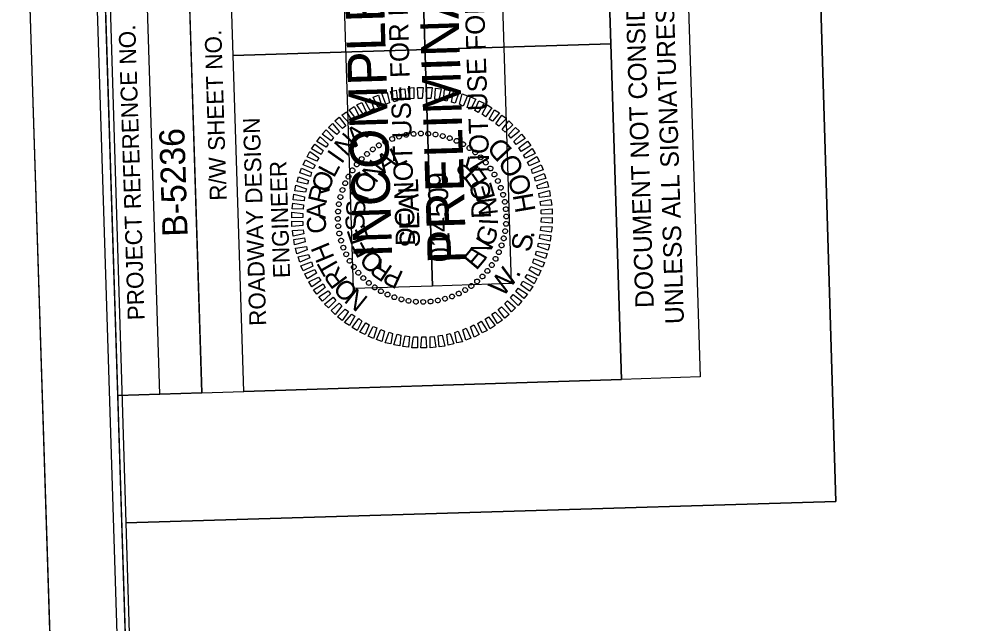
# Model space of a CAD drawing. Extents: x 2326025 to 2327173, y 123144 to 125024.
# Drawn here: x 2326025.5 to 2326312.3, y 124704.9 to 124884.9 of the extents above; entities that cross this region are included whole.
import ezdxf

# ---------------------------------------------------------------- set-up
doc = ezdxf.new("R2010")
doc.units = 0
for name, color, linetype in [('Sheet Clip Boundary CELL', 7, 'Continuous'), ('Sheet Cutting Line CELL', 7, 'Continuous'), ('Sheet Data Field CELL', 7, 'Continuous'), ('Sheet Layout Plan Border', 7, 'Continuous'), ('Sheet PE Seal Cell', 7, 'Continuous'), ('Sheet Plan CELL', 7, 'Continuous'), ('Sheet Plan Layout CELL', 7, 'Continuous'), ('Sheet Plot Border Inside CELL', 7, 'Continuous'), ('Sheet Plot Border Outside CELL', 7, 'Continuous'), ('Sheet Sticker Exception Certification CELL', 7, 'Continuous'), ('Sheet Sticker Incomplete CELL', 7, 'Continuous'), ('Sheet Sticker Preliminary CELL', 7, 'Continuous'), ('Typical Detail Wedge2 CELL', 7, 'Continuous')]:
    doc.layers.add(name, color=color, linetype=linetype)

msp = doc.modelspace()

# ---------------------------------------------------------------- linework, layer by layer
at = {"layer": 'Sheet Clip Boundary CELL'}
msp.add_lwpolyline([(2327143.22, 123556.44), (2327101.01, 124955.82), (2326262.87, 124930.53), (2326268.58, 124741.36), (2326057.19, 124734.98), (2326093.7, 123524.78)], close=True, dxfattribs=at)
at = {"layer": 'Sheet Cutting Line CELL'}
msp.add_line((2326025.47, 124989.14), (2326078.49, 123306.48), dxfattribs=at)
at = {"layer": 'Sheet Layout Plan Border'}
msp.add_lwpolyline([(2327143.22, 123556.44), (2327101.01, 124955.82), (2326262.87, 124930.53), (2326268.58, 124741.36), (2326057.19, 124734.98), (2326093.7, 123524.78)], close=True, dxfattribs=at)
at = {"layer": 'Sheet PE Seal Cell'}
for p, q in [((2326134.48, 124848.43), (2326134.48, 124848.43)), ((2326136.45, 124849.3), (2326136.45, 124849.3)), ((2326138.53, 124849.96), (2326138.53, 124849.96)), ((2326140.72, 124850.43), (2326140.72, 124850.43)), ((2326142.86, 124850.8), (2326142.86, 124850.8)), ((2326145.06, 124850.92), (2326145.06, 124850.92)), ((2326147.26, 124850.84), (2326147.26, 124850.84)), ((2326149.42, 124850.56), (2326149.42, 124850.56)), ((2326151.53, 124850.17), (2326151.53, 124850.17)), ((2326153.66, 124849.54), (2326153.66, 124849.54)), ((2326155.68, 124848.7), (2326155.68, 124848.7)), ((2326130.7, 124846.16), (2326130.7, 124846.16)), ((2326132.56, 124847.37), (2326132.56, 124847.37)), ((2326157.66, 124847.76), (2326157.66, 124847.76)), ((2326159.5, 124846.57), (2326159.5, 124846.57)), ((2326127.39, 124843.31), (2326127.39, 124843.31)), ((2326128.99, 124844.86), (2326128.99, 124844.86)), ((2326161.29, 124845.28), (2326161.29, 124845.28)), ((2326162.89, 124843.83), (2326162.89, 124843.83)), ((2326124.64, 124839.92), (2326124.64, 124839.92)), ((2326125.94, 124841.71), (2326125.94, 124841.71)), ((2326164.44, 124842.22), (2326164.44, 124842.22)), ((2326165.75, 124840.52), (2326165.75, 124840.52)), ((2326123.45, 124838.08), (2326123.45, 124838.08)), ((2326166.95, 124838.65), (2326166.95, 124838.65)), ((2326121.68, 124834.07), (2326121.68, 124834.07)), ((2326122.51, 124836.1), (2326122.51, 124836.1)), ((2326168.02, 124836.73), (2326168.02, 124836.73)), ((2326168.88, 124834.76), (2326168.88, 124834.76)), ((2326121.04, 124831.95), (2326121.04, 124831.95)), ((2326169.54, 124832.68), (2326169.54, 124832.68)), ((2326120.66, 124829.84), (2326120.66, 124829.84)), ((2326170.01, 124830.49), (2326170.01, 124830.49)), ((2326170.38, 124828.35), (2326170.38, 124828.35)), ((2326120.3, 124825.48), (2326120.3, 124825.48)), ((2326120.38, 124827.68), (2326120.38, 124827.68)), ((2326145.4, 124825.82), (2326145.4, 124825.82)), ((2326170.5, 124826.16), (2326170.5, 124826.16)), ((2326120.42, 124823.28), (2326120.42, 124823.28)), ((2326170.42, 124823.95), (2326170.42, 124823.95)), ((2326120.78, 124821.14), (2326120.78, 124821.14)), ((2326169.75, 124819.68), (2326169.75, 124819.68)), ((2326170.14, 124821.79), (2326170.14, 124821.79)), ((2326121.25, 124818.95), (2326121.25, 124818.95)), ((2326121.92, 124816.87), (2326121.92, 124816.87)), ((2326169.12, 124817.56), (2326169.12, 124817.56)), ((2326122.78, 124814.9), (2326122.78, 124814.9)), ((2326168.28, 124815.53), (2326168.28, 124815.53)), ((2326123.84, 124812.98), (2326123.84, 124812.98)), ((2326125.05, 124811.12), (2326125.05, 124811.12)), ((2326166.15, 124811.71), (2326166.15, 124811.71)), ((2326167.35, 124813.55), (2326167.35, 124813.55)), ((2326126.36, 124809.41), (2326126.36, 124809.41)), ((2326163.41, 124808.33), (2326163.41, 124808.33)), ((2326164.86, 124809.92), (2326164.86, 124809.92)), ((2326127.91, 124807.81), (2326127.91, 124807.81)), ((2326129.5, 124806.36), (2326129.5, 124806.36)), ((2326160.1, 124805.47), (2326160.1, 124805.47)), ((2326161.81, 124806.77), (2326161.81, 124806.77)), ((2326131.29, 124805.06), (2326131.29, 124805.06)), ((2326133.13, 124803.87), (2326133.13, 124803.87)), ((2326135.11, 124802.93), (2326135.11, 124802.93)), ((2326156.32, 124803.2), (2326156.32, 124803.2)), ((2326158.23, 124804.26), (2326158.23, 124804.26)), ((2326137.14, 124802.1), (2326137.14, 124802.1)), ((2326139.26, 124801.46), (2326139.26, 124801.46)), ((2326141.38, 124801.08), (2326141.38, 124801.08)), ((2326143.54, 124800.8), (2326143.54, 124800.8)), ((2326145.74, 124800.72), (2326145.74, 124800.72)), ((2326147.94, 124800.83), (2326147.94, 124800.83)), ((2326150.08, 124801.2), (2326150.08, 124801.2)), ((2326152.26, 124801.67), (2326152.26, 124801.67)), ((2326154.34, 124802.34), (2326154.34, 124802.34))]:
    msp.add_line(p, q, dxfattribs=at)
for points in [[(2326134.63, 124859.59), (2326133.38, 124862.76), (2326135.02, 124863.11), (2326135.67, 124859.98)], [(2326137.01, 124860.27), (2326135.96, 124863.39), (2326137.65, 124863.74), (2326138.05, 124860.6)], [(2326139.39, 124860.8), (2326138.59, 124864.02), (2326140.29, 124864.22), (2326140.59, 124861.03)], [(2326141.78, 124861.17), (2326141.28, 124864.41), (2326142.98, 124864.56), (2326142.98, 124861.31)], [(2326144.28, 124861.3), (2326144.03, 124864.54), (2326145.73, 124864.6), (2326145.48, 124861.34)], [(2326146.78, 124861.33), (2326146.78, 124864.58), (2326148.43, 124864.53), (2326147.98, 124861.27)], [(2326149.19, 124861.15), (2326149.39, 124864.36), (2326151.09, 124864.22), (2326150.39, 124860.94)], [(2326151.75, 124860.83), (2326152.05, 124863.95), (2326153.76, 124863.65), (2326152.81, 124860.47)], [(2326154.17, 124860.26), (2326154.72, 124863.38), (2326156.38, 124863.08), (2326155.23, 124859.89)], [(2326156.59, 124859.59), (2326157.39, 124862.71), (2326158.96, 124862.11), (2326157.66, 124859.07)], [(2326127.82, 124856.68), (2326125.98, 124859.42), (2326127.51, 124860.12), (2326128.75, 124857.31)], [(2326129.94, 124857.75), (2326128.34, 124860.65), (2326129.92, 124861.35), (2326131.02, 124858.28)], [(2326132.26, 124858.72), (2326130.86, 124861.73), (2326132.39, 124862.33), (2326133.29, 124859.25)], [(2326158.82, 124858.66), (2326159.87, 124861.79), (2326161.45, 124861.09), (2326159.94, 124858.19)], [(2326161.15, 124857.73), (2326162.31, 124860.62), (2326163.88, 124859.92), (2326162.12, 124857.16)], [(2326123.65, 124853.95), (2326121.48, 124856.33), (2326122.89, 124857.32), (2326124.58, 124854.58)], [(2326125.66, 124855.31), (2326123.68, 124857.9), (2326125.15, 124858.9), (2326126.64, 124856.04)], [(2326163.34, 124856.6), (2326164.75, 124859.44), (2326166.18, 124858.49), (2326164.26, 124855.83)], [(2326165.38, 124855.16), (2326167, 124857.91), (2326168.48, 124857.01), (2326166.35, 124854.54)], [(2326121.75, 124852.39), (2326119.43, 124854.61), (2326120.74, 124855.71), (2326122.73, 124853.12)], [(2326167.33, 124853.72), (2326169.2, 124856.38), (2326170.53, 124855.32), (2326168.25, 124853.05)], [(2326169.28, 124852.03), (2326171.25, 124854.65), (2326172.44, 124853.43), (2326170.11, 124851.26)], [(2326118.31, 124848.73), (2326115.65, 124850.69), (2326116.81, 124851.93), (2326119.03, 124849.7)], [(2326120.01, 124850.58), (2326117.59, 124852.65), (2326118.75, 124853.89), (2326120.78, 124851.35)], [(2326171.09, 124850.44), (2326173.22, 124852.71), (2326174.45, 124851.54), (2326171.82, 124849.51)], [(2326116.82, 124846.78), (2326114.02, 124848.54), (2326115.08, 124849.87), (2326117.49, 124847.75)], [(2326172.7, 124848.49), (2326175.03, 124850.71), (2326176.12, 124849.4), (2326173.38, 124847.56)], [(2326174.26, 124846.64), (2326176.75, 124848.57), (2326177.74, 124847.3), (2326174.89, 124845.56)], [(2326114.1, 124842.69), (2326111.21, 124843.95), (2326112.01, 124845.48), (2326114.67, 124843.66)], [(2326115.39, 124844.68), (2326112.44, 124846.34), (2326113.44, 124847.67), (2326115.95, 124845.8)], [(2326175.58, 124844.48), (2326178.22, 124846.41), (2326179.06, 124844.89), (2326176.21, 124843.55)], [(2326113.02, 124840.35), (2326110.04, 124841.51), (2326110.69, 124843.08), (2326113.54, 124841.47)], [(2326176.84, 124842.37), (2326179.59, 124844.05), (2326180.34, 124842.53), (2326177.33, 124841.28)], [(2326112.15, 124838.08), (2326108.96, 124839.13), (2326109.52, 124840.54), (2326112.46, 124839.24)], [(2326177.96, 124840.2), (2326180.82, 124841.59), (2326181.47, 124840.11), (2326178.3, 124838.96)], [(2326111.32, 124835.8), (2326108.19, 124836.45), (2326108.65, 124838.02), (2326111.63, 124836.86)], [(2326178.84, 124837.78), (2326181.8, 124839.02), (2326182.3, 124837.48), (2326179.22, 124836.74)], [(2326110.74, 124833.38), (2326107.48, 124833.78), (2326107.83, 124835.49), (2326110.96, 124834.44)], [(2326179.56, 124835.4), (2326182.68, 124836.55), (2326183.08, 124834.86), (2326179.85, 124834.36)], [(2326110.27, 124830.81), (2326107.06, 124831.16), (2326107.26, 124832.82), (2326110.39, 124832.02)], [(2326180.19, 124833.02), (2326183.36, 124833.92), (2326183.56, 124832.27), (2326180.38, 124831.82)], [(2326180.56, 124830.63), (2326183.75, 124831.28), (2326184, 124829.58), (2326180.75, 124829.43)], [(2326109.95, 124828.4), (2326106.69, 124828.5), (2326106.94, 124830.16), (2326110.11, 124829.61)], [(2326180.89, 124828.14), (2326184.13, 124828.49), (2326184.14, 124826.84), (2326180.88, 124826.93)], [(2326109.88, 124825.9), (2326106.63, 124825.8), (2326106.63, 124827.45), (2326109.89, 124827.1)], [(2326180.92, 124825.74), (2326184.17, 124825.84), (2326184.17, 124824.19), (2326180.91, 124824.53)], [(2326109.9, 124823.5), (2326106.66, 124823.15), (2326106.66, 124824.8), (2326109.92, 124824.7)], [(2326180.85, 124823.23), (2326184.1, 124823.13), (2326183.85, 124821.48), (2326180.69, 124822.03)], [(2326110.23, 124821.01), (2326107.05, 124820.36), (2326106.8, 124822.05), (2326110.04, 124822.2)], [(2326110.61, 124818.62), (2326107.43, 124817.72), (2326107.23, 124819.36), (2326110.42, 124819.81)], [(2326180.52, 124820.82), (2326183.74, 124820.47), (2326183.54, 124818.81), (2326180.41, 124819.62)], [(2326111.23, 124816.24), (2326108.12, 124815.09), (2326107.71, 124816.78), (2326110.95, 124817.28)], [(2326180.05, 124818.25), (2326183.32, 124817.86), (2326182.97, 124816.15), (2326179.84, 124817.2)], [(2326111.96, 124813.86), (2326109, 124812.61), (2326108.5, 124814.15), (2326111.58, 124814.9)], [(2326179.48, 124815.84), (2326182.6, 124815.18), (2326182.15, 124813.62), (2326179.16, 124814.77)], [(2326112.84, 124811.43), (2326109.98, 124810.04), (2326109.33, 124811.52), (2326112.5, 124812.67)], [(2326177.77, 124811.28), (2326180.76, 124810.12), (2326180.11, 124808.55), (2326177.26, 124810.16)], [(2326178.65, 124813.56), (2326181.84, 124812.51), (2326181.28, 124811.09), (2326178.34, 124812.4)], [(2326113.95, 124809.27), (2326111.21, 124807.58), (2326110.46, 124809.11), (2326113.47, 124810.35)], [(2326176.7, 124808.94), (2326179.59, 124807.68), (2326178.78, 124806.16), (2326176.13, 124807.98)], [(2326115.22, 124807.16), (2326112.58, 124805.22), (2326111.73, 124806.75), (2326114.59, 124808.09)], [(2326116.54, 124805), (2326114.05, 124803.07), (2326113.06, 124804.34), (2326115.91, 124806.08)], [(2326175.41, 124806.95), (2326178.36, 124805.29), (2326177.35, 124803.96), (2326174.84, 124805.83)], [(2326118.1, 124803.15), (2326115.77, 124800.92), (2326114.68, 124802.24), (2326117.42, 124804.07)], [(2326172.48, 124802.91), (2326175.15, 124800.94), (2326173.98, 124799.7), (2326171.76, 124801.94)], [(2326173.97, 124804.86), (2326176.78, 124803.09), (2326175.72, 124801.76), (2326173.3, 124803.88)], [(2326119.71, 124801.2), (2326117.58, 124798.93), (2326116.34, 124800.09), (2326118.98, 124802.12)], [(2326121.51, 124799.6), (2326119.54, 124796.99), (2326118.35, 124798.2), (2326120.69, 124800.38)], [(2326170.79, 124801.05), (2326173.21, 124798.98), (2326172.05, 124797.74), (2326170.01, 124800.28)], [(2326123.47, 124797.91), (2326121.6, 124795.25), (2326120.27, 124796.31), (2326122.54, 124798.58)], [(2326125.41, 124796.47), (2326123.8, 124793.72), (2326122.32, 124794.62), (2326124.44, 124797.09)], [(2326167.15, 124797.69), (2326169.32, 124795.31), (2326167.9, 124794.31), (2326166.21, 124797.06)], [(2326169.05, 124799.25), (2326171.37, 124797.02), (2326170.05, 124795.93), (2326168.07, 124798.52)], [(2326127.46, 124795.04), (2326126.05, 124792.19), (2326124.62, 124793.15), (2326126.53, 124795.81)], [(2326129.65, 124793.9), (2326128.49, 124791.02), (2326126.91, 124791.72), (2326128.68, 124794.47)], [(2326160.86, 124793.89), (2326162.45, 124790.99), (2326160.88, 124790.29), (2326159.78, 124793.35)], [(2326162.98, 124794.96), (2326164.82, 124792.21), (2326163.29, 124791.51), (2326162.05, 124794.33)], [(2326165.14, 124796.32), (2326167.12, 124793.74), (2326165.65, 124792.74), (2326164.16, 124795.59)], [(2326131.98, 124792.98), (2326130.92, 124789.84), (2326129.35, 124790.54), (2326130.86, 124793.44)], [(2326134.21, 124792.05), (2326133.4, 124788.92), (2326131.83, 124789.52), (2326133.14, 124792.56)], [(2326136.63, 124791.37), (2326136.08, 124788.25), (2326134.42, 124788.55), (2326135.57, 124791.74)], [(2326139.05, 124790.8), (2326138.75, 124787.69), (2326137.04, 124787.98), (2326137.99, 124791.17)], [(2326153.79, 124791.36), (2326154.84, 124788.25), (2326153.15, 124787.89), (2326152.75, 124791.03)], [(2326156.17, 124792.04), (2326157.42, 124788.88), (2326155.78, 124788.53), (2326155.13, 124791.66)], [(2326158.54, 124792.91), (2326159.94, 124789.91), (2326158.4, 124789.31), (2326157.51, 124792.38)], [(2326141.61, 124790.48), (2326141.41, 124787.27), (2326139.7, 124787.42), (2326140.4, 124790.69)], [(2326144.02, 124790.31), (2326144.02, 124787.05), (2326142.37, 124787.1), (2326142.81, 124790.37)], [(2326146.52, 124790.33), (2326146.77, 124787.09), (2326145.07, 124787.04), (2326145.32, 124790.3)], [(2326149.01, 124790.46), (2326149.52, 124787.23), (2326147.82, 124787.07), (2326147.82, 124790.33)], [(2326151.4, 124790.84), (2326152.2, 124787.61), (2326150.51, 124787.41), (2326150.21, 124790.6)]]:
    msp.add_lwpolyline(points, close=True, dxfattribs=at)
for centre, major_axis in [((2326140.7, 124850.45), (-0.135, 0.707)), ((2326142.86, 124850.77), (-0.073, 0.716)), ((2326145.05, 124850.89), (-0.01, 0.72)), ((2326147.23, 124850.83), (0.053, 0.718)), ((2326149.41, 124850.57), (0.115, 0.711)), ((2326134.48, 124848.4), (-0.313, 0.648)), ((2326136.49, 124849.26), (-0.256, 0.673)), ((2326138.57, 124849.95), (-0.196, 0.693)), ((2326151.55, 124850.13), (0.177, 0.698)), ((2326153.64, 124849.5), (0.237, 0.68)), ((2326155.68, 124848.69), (0.295, 0.657)), ((2326157.63, 124847.71), (0.351, 0.629)), ((2326129.01, 124844.8), (-0.471, 0.545)), ((2326130.73, 124846.16), (-0.421, 0.584)), ((2326132.55, 124847.36), (-0.369, 0.618)), ((2326159.49, 124846.56), (0.405, 0.596)), ((2326161.25, 124845.25), (0.455, 0.558)), ((2326127.42, 124843.3), (-0.516, 0.502)), ((2326162.88, 124843.8), (0.502, 0.516)), ((2326164.38, 124842.21), (0.545, 0.471)), ((2326124.65, 124839.91), (-0.596, 0.405)), ((2326125.96, 124841.67), (-0.558, 0.455)), ((2326165.74, 124840.49), (0.584, 0.421)), ((2326122.52, 124836.1), (-0.657, 0.295)), ((2326123.5, 124838.05), (-0.629, 0.351)), ((2326166.94, 124838.66), (0.618, 0.369)), ((2326167.98, 124836.73), (0.648, 0.313)), ((2326121.71, 124834.06), (-0.68, 0.237)), ((2326168.84, 124834.72), (0.673, 0.256)), ((2326121.08, 124831.97), (-0.698, 0.177)), ((2326169.53, 124832.65), (0.693, 0.196)), ((2326170.03, 124830.52), (0.707, 0.135)), ((2326120.39, 124827.65), (-0.718, 0.053)), ((2326120.64, 124829.82), (-0.711, 0.115)), ((2326170.35, 124828.35), (0.716, 0.073)), ((2326120.32, 124825.46), (-0.72, -0.01)), ((2326170.48, 124826.17), (0.72, 0.01)), ((2326120.45, 124823.28), (-0.716, -0.073)), ((2326170.16, 124821.81), (0.711, -0.115)), ((2326170.41, 124823.98), (0.718, -0.053)), ((2326120.76, 124821.12), (-0.707, -0.135)), ((2326121.27, 124818.99), (-0.693, -0.196)), ((2326169.71, 124819.67), (0.698, -0.177)), ((2326121.95, 124816.91), (-0.673, -0.256)), ((2326169.08, 124817.57), (0.68, -0.237)), ((2326122.82, 124814.9), (-0.648, -0.313)), ((2326167.29, 124813.58), (0.629, -0.351)), ((2326168.28, 124815.54), (0.657, -0.295)), ((2326123.86, 124812.97), (-0.618, -0.369)), ((2326125.06, 124811.14), (-0.584, -0.421)), ((2326166.14, 124811.72), (0.596, -0.405)), ((2326126.41, 124809.43), (-0.545, -0.471)), ((2326127.91, 124807.84), (-0.502, -0.516)), ((2326163.38, 124808.33), (0.516, -0.502)), ((2326164.84, 124809.97), (0.558, -0.455)), ((2326129.55, 124806.38), (-0.455, -0.558)), ((2326131.3, 124805.07), (-0.405, -0.596)), ((2326160.07, 124805.48), (0.421, -0.584)), ((2326161.79, 124806.83), (0.471, -0.545)), ((2326133.16, 124803.92), (-0.351, -0.629)), ((2326135.12, 124802.94), (-0.295, -0.657)), ((2326137.15, 124802.13), (-0.237, -0.68)), ((2326152.23, 124801.69), (0.196, -0.693)), ((2326154.31, 124802.37), (0.256, -0.673)), ((2326156.32, 124803.24), (0.313, -0.648)), ((2326158.24, 124804.28), (0.369, -0.618)), ((2326139.25, 124801.5), (-0.177, -0.698)), ((2326141.39, 124801.06), (-0.115, -0.711)), ((2326143.56, 124800.8), (-0.053, -0.718)), ((2326145.75, 124800.74), (0.01, -0.72)), ((2326147.93, 124800.87), (0.073, -0.716)), ((2326150.1, 124801.18), (0.135, -0.707))]:
    msp.add_ellipse(centre, major_axis=major_axis, ratio=0.999708, dxfattribs=at)
at = {"layer": 'Sheet Plan CELL'}
for p, q in [((2326067.31, 124773.29), (2326061.02, 124973.24)), ((2326079.84, 124773.7), (2326073.52, 124973.64)), ((2326079.84, 124773.7), (2326073.52, 124973.64)), ((2326089.17, 124874.09), (2326201.58, 124877.65)), ((2326079.84, 124773.7), (2326092.32, 124774.09))]:
    msp.add_line(p, q, dxfattribs=at)
for points in [[(2326048.48, 124972.88), (2326095.72, 123473.59), (2327145.2, 123506.66), (2327097.96, 125005.93)], [(2327145.2, 123506.66), (2326095.75, 123473.57), (2326054.77, 124772.91), (2326204.76, 124777.65), (2326198.47, 124977.58), (2327097.96, 125005.93)], [(2326089.17, 124874.09), (2326086.01, 124974.03), (2326198.47, 124977.58), (2326201.63, 124877.63)], [(2326054.77, 124772.91), (2326048.48, 124972.88), (2326073.52, 124973.64), (2326079.84, 124773.7)], [(2326092.32, 124774.09), (2326089.17, 124874.09), (2326201.63, 124877.63), (2326204.76, 124777.65)]]:
    msp.add_lwpolyline(points, close=True, dxfattribs=at)
at = {"layer": 'Sheet Plan Layout CELL'}
for points in [[(2326095.24, 123474.78), (2327144.73, 123506.47), (2327099.5, 125005.78), (2326261.37, 124980.5), (2326268.58, 124741.36), (2326057.19, 124734.98)], [(2326268.58, 124741.36), (2326261.37, 124980.52), (2326049.97, 124974.17), (2326057.19, 124734.98)]]:
    msp.add_lwpolyline(points, close=True, dxfattribs=at)
at = {"layer": 'Sheet Plot Border Inside CELL'}
msp.add_lwpolyline([(2327152.55, 123353.33), (2327100.07, 125018.49), (2326045.6, 124985.27), (2326098.07, 123320.1)], close=True, dxfattribs=at)
at = {"layer": 'Sheet Plot Border Outside CELL'}
msp.add_lwpolyline([(2327172.95, 123340.96), (2327119.93, 125023.63), (2326025.47, 124989.14), (2326078.49, 123306.48)], close=True, dxfattribs=at)
at = {"layer": 'Sheet Sticker Exception Certification CELL'}
for p, q in [((2326204.76, 124777.65), (2326198.46, 124977.58)), ((2326221.94, 124978.32), (2326228.24, 124778.39)), ((2326228.24, 124778.39), (2326204.76, 124777.65))]:
    msp.add_line(p, q, dxfattribs=at)
at = {"layer": 'Sheet Sticker Incomplete CELL'}
msp.add_lwpolyline([(2326148.48, 124805.44), (2326124.99, 124804.7), (2326120.36, 124951.63), (2326143.85, 124952.37)], close=True, dxfattribs=at)
at = {"layer": 'Sheet Sticker Preliminary CELL'}
msp.add_lwpolyline([(2326171.97, 124806.18), (2326148.48, 124805.44), (2326143.85, 124952.37), (2326167.34, 124953.11)], close=True, dxfattribs=at)

# ---------------------------------------------------------------- texts
at = {"layer": 'Sheet Data Field CELL'}
msp.add_text('B-5236', height=7.5, rotation=91.8048, dxfattribs=at).set_placement((2326075.61, 124820.26))
at = {"layer": 'Sheet PE Seal Cell'}
for s, height, rotation, p in [('A', 5.64, 40.4219, (2326125.78, 124846.81)), ('N', 5.64, 47.6237, (2326122.92, 124843.77)), ('I', 5.64, 54.8249, (2326121.44, 124841.57)), ('L', 5.64, 24.2056, (2326137.47, 124840.82)), ('N', 5.64, 52.2814, (2326131.58, 124835.84)), ('A', 5.64, 33.5651, (2326134.08, 124838.77)), ('R', 5.64, 134.2862, (2326162.7, 124840.47)), ('L', 5.64, 62.0257, (2326119.17, 124837.45)), ('E', 5.64, 124.9289, (2326165.16, 124836.99)), ('O', 5.64, 69.226, (2326117.46, 124832.99)), ('O', 5.64, 61.6383, (2326129.68, 124832.43)), ('SEAL', 5.998, 91.8048, (2326144.83, 124817)), ('014509', 5.998, 91.8048, (2326153.82, 124812.69)), ('R', 5.64, 76.4259, (2326116.81, 124829.62)), ('E', 5.64, 106.2166, (2326167.27, 124831.76)), ('I', 5.64, 70.9944, (2326129.05, 124830.4)), ('N', 5.64, 96.8612, (2326168.03, 124826.83)), ('A', 5.64, 90.8251, (2326116.75, 124825.41)), ('S', 5.64, 89.7052, (2326128.48, 124826.08)), ('C', 5.64, 98.0247, (2326117.17, 124821.48)), ('S', 5.64, 99.0604, (2326128.64, 124822.49)), ('E', 5.64, 108.4159, (2326129.8, 124819.07)), ('G', 5.64, 68.795, (2326166.29, 124816.87)), ('I', 5.64, 87.506, (2326167.98, 124823.48)), ('N', 5.64, 59.4387, (2326164.16, 124813)), ('H', 5.64, 112.4243, (2326119.41, 124813.94)), ('F', 5.64, 117.7718, (2326131.4, 124815.92)), ('E', 5.64, 50.0817, (2326161.56, 124809.92)), ('O', 5.64, 136.486, (2326134.46, 124812.72)), ('R', 5.64, 145.8444, (2326136.96, 124811.04)), ('T', 5.64, 119.6246, (2326121.16, 124810.75)), ('R', 5.64, 126.8253, (2326123.47, 124807.42)), ('P', 5.64, 155.2037, (2326140.21, 124809.55)), ('O', 5.64, 134.0265, (2326126.67, 124804.07)), ('N', 5.64, 141.2283, (2326129.65, 124801.86))]:
    msp.add_text(s, height=height, rotation=rotation, dxfattribs=at).set_placement(p)
at = {"layer": 'Sheet Plan CELL'}
for s, height, p in [('PROJECT REFERENCE NO.', 5.0001, (2326062.79, 124795.37)), ('R/W SHEET NO.', 5.0001, (2326087.23, 124830.96)), ('ROADWAY DESIGN', 5.0001, (2326099.01, 124793.69)), ('ENGINEER', 5, (2326106.1, 124807.9))]:
    msp.add_text(s, height=height, rotation=91.8048, dxfattribs=at).set_placement(p)
at = {"layer": 'Sheet Sticker Exception Certification CELL'}
for s, p in [('UNLESS ALL SIGNATURES COMPLETED', (2326223.39, 124794.24)), ('DOCUMENT NOT CONSIDERED FINAL', (2326214.43, 124799.03))]:
    msp.add_text(s, height=5.5, rotation=91.8048, dxfattribs=at).set_placement(p)
at = {"layer": 'Sheet Sticker Incomplete CELL'}
for s, height, p in [('INCOMPLETE PLANS', 11.52, (2326136.51, 124814.02)), ('DO NOT USE FOR R/W ACQUISITION', 5.76, (2326143.35, 124817.49))]:
    msp.add_text(s, height=height, rotation=91.8048, dxfattribs=at).set_placement(p)
at = {"layer": 'Sheet Sticker Preliminary CELL'}
for s, height, p in [('PRELIMINARY PLANS', 11.52, (2326158.62, 124812.26)), ('DO NOT USE FOR CONSTRUCTION', 5.76, (2326165.91, 124825.6))]:
    msp.add_text(s, height=height, rotation=91.8048, dxfattribs=at).set_placement(p)
at = {"layer": 'Typical Detail Wedge2 CELL'}
for s, rotation, p in [('D', 132.8577, (2326172.61, 124846.04)), ('O', 121.2972, (2326176.11, 124840.17)), ('O', 109.7368, (2326178.36, 124833.73)), ('H', 99.7529, (2326179.24, 124827.89)), ('S', 78.193, (2326177.63, 124815.31)), ('.', 85.5187, (2326178.71, 124819.51)), ('W', 51.4248, (2326169.45, 124801.92)), ('.', 63.9589, (2326174.06, 124807.71))]:
    msp.add_text(s, height=6, rotation=rotation, dxfattribs=at).set_placement(p)

doc.saveas('drawing.dxf')
